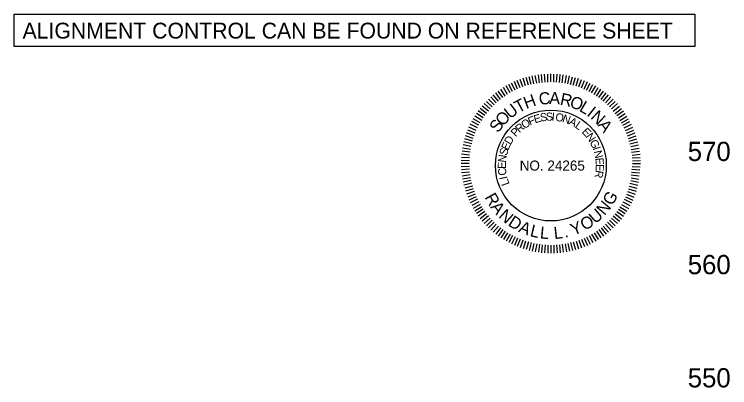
# Model space of a CAD drawing. Extents: x 1964377 to 1966966, y 1116414 to 1123213.
# Drawn here: x 1966634 to 1966949.9, y 1121376.7 to 1121541.6 of the extents above; entities that cross this region are included whole.
import ezdxf

# ---------------------------------------------------------------- set-up
doc = ezdxf.new("R2010")
doc.units = 0
for name, color, linetype in [('RD_DDB_Profile_Elev', 7, 'Continuous'), ('RD_Sketch1', 7, 'Continuous'), ('RD_TX_PEShield', 7, 'Continuous')]:
    doc.layers.add(name, color=color, linetype=linetype)

msp = doc.modelspace()

# ---------------------------------------------------------------- linework, layer by layer
at = {"layer": 'RD_Sketch1'}
msp.add_lwpolyline([(1966634.01, 1121541.61), (1966934.43, 1121541.61), (1966934.43, 1121527.35), (1966634.01, 1121527.35)], close=True, dxfattribs=at)
at = {"layer": 'RD_TX_PEShield'}
for p, q in [((1966869.64, 1121511.65), (1966869.52, 1121515.21)), ((1966869.64, 1121511.65), (1966869.52, 1121515.21)), ((1966870.9, 1121511.72), (1966870.9, 1121515.28)), ((1966870.9, 1121511.72), (1966870.9, 1121515.28)), ((1966872.15, 1121511.65), (1966872.28, 1121515.21)), ((1966872.15, 1121511.65), (1966872.28, 1121515.21)), ((1966857.41, 1121509.06), (1966856.08, 1121512.35)), ((1966857.41, 1121509.06), (1966856.08, 1121512.35)), ((1966858.59, 1121509.51), (1966857.37, 1121512.85)), ((1966858.59, 1121509.51), (1966857.37, 1121512.85)), ((1966859.76, 1121509.96), (1966858.66, 1121513.34)), ((1966859.76, 1121509.96), (1966858.66, 1121513.34)), ((1966860.98, 1121510.28), (1966860, 1121513.7)), ((1966860.98, 1121510.28), (1966860, 1121513.7)), ((1966862.19, 1121510.61), (1966861.33, 1121514.06)), ((1966862.19, 1121510.61), (1966861.33, 1121514.06)), ((1966863.4, 1121510.93), (1966862.66, 1121514.41)), ((1966863.4, 1121510.93), (1966862.66, 1121514.41)), ((1966864.65, 1121511.13), (1966864.03, 1121514.63)), ((1966864.65, 1121511.13), (1966864.03, 1121514.63)), ((1966865.89, 1121511.33), (1966865.39, 1121514.85)), ((1966865.89, 1121511.33), (1966865.39, 1121514.85)), ((1966867.13, 1121511.52), (1966866.76, 1121515.06)), ((1966867.13, 1121511.52), (1966866.76, 1121515.06)), ((1966868.39, 1121511.59), (1966868.14, 1121515.14)), ((1966868.39, 1121511.59), (1966868.14, 1121515.14)), ((1966873.41, 1121511.59), (1966873.66, 1121515.14)), ((1966873.41, 1121511.59), (1966873.66, 1121515.14)), ((1966874.67, 1121511.52), (1966875.04, 1121515.06)), ((1966874.67, 1121511.52), (1966875.04, 1121515.06)), ((1966875.91, 1121511.33), (1966876.4, 1121514.85)), ((1966875.91, 1121511.33), (1966876.4, 1121514.85)), ((1966877.15, 1121511.13), (1966877.77, 1121514.63)), ((1966877.15, 1121511.13), (1966877.77, 1121514.63)), ((1966878.39, 1121510.93), (1966879.13, 1121514.41)), ((1966878.39, 1121510.93), (1966879.13, 1121514.41)), ((1966878.39, 1121510.93), (1966879.13, 1121514.41)), ((1966879.61, 1121510.61), (1966880.47, 1121514.06)), ((1966879.61, 1121510.61), (1966880.47, 1121514.06)), ((1966879.61, 1121510.61), (1966880.47, 1121514.06)), ((1966880.82, 1121510.28), (1966881.8, 1121513.7)), ((1966880.82, 1121510.28), (1966881.8, 1121513.7)), ((1966880.82, 1121510.28), (1966881.8, 1121513.7)), ((1966882.04, 1121509.96), (1966883.14, 1121513.34)), ((1966882.04, 1121509.96), (1966883.14, 1121513.34)), ((1966882.04, 1121509.96), (1966883.14, 1121513.34)), ((1966883.21, 1121509.51), (1966884.43, 1121512.85)), ((1966883.21, 1121509.51), (1966884.43, 1121512.85)), ((1966883.21, 1121509.51), (1966884.43, 1121512.85)), ((1966884.38, 1121509.06), (1966885.72, 1121512.35)), ((1966884.38, 1121509.06), (1966885.72, 1121512.35)), ((1966884.38, 1121509.06), (1966885.72, 1121512.35)), ((1966851.82, 1121506.21), (1966849.94, 1121509.22)), ((1966851.82, 1121506.21), (1966849.94, 1121509.22)), ((1966852.88, 1121506.89), (1966851.1, 1121509.97)), ((1966852.88, 1121506.89), (1966851.1, 1121509.97)), ((1966854, 1121507.46), (1966852.33, 1121510.6)), ((1966854, 1121507.46), (1966852.33, 1121510.6)), ((1966855.12, 1121508.03), (1966853.56, 1121511.23)), ((1966855.12, 1121508.03), (1966853.56, 1121511.23)), ((1966856.24, 1121508.6), (1966854.79, 1121511.86)), ((1966856.24, 1121508.6), (1966854.79, 1121511.86)), ((1966885.56, 1121508.6), (1966887.01, 1121511.86)), ((1966885.56, 1121508.6), (1966887.01, 1121511.86)), ((1966885.56, 1121508.6), (1966887.01, 1121511.86)), ((1966886.68, 1121508.03), (1966888.24, 1121511.23)), ((1966886.68, 1121508.03), (1966888.24, 1121511.23)), ((1966886.68, 1121508.03), (1966888.24, 1121511.23)), ((1966887.8, 1121507.46), (1966889.47, 1121510.6)), ((1966887.8, 1121507.46), (1966889.47, 1121510.6)), ((1966887.8, 1121507.46), (1966889.47, 1121510.6)), ((1966888.92, 1121506.89), (1966890.7, 1121509.97)), ((1966888.92, 1121506.89), (1966890.7, 1121509.97)), ((1966888.92, 1121506.89), (1966890.7, 1121509.97)), ((1966889.98, 1121506.21), (1966891.86, 1121509.22)), ((1966889.98, 1121506.21), (1966891.86, 1121509.22)), ((1966889.98, 1121506.21), (1966891.86, 1121509.22)), ((1966847.76, 1121503.25), (1966845.47, 1121505.98)), ((1966847.76, 1121503.25), (1966845.47, 1121505.98)), ((1966848.73, 1121504.04), (1966846.54, 1121506.85)), ((1966848.73, 1121504.04), (1966846.54, 1121506.85)), ((1966849.71, 1121504.84), (1966847.62, 1121507.72)), ((1966849.71, 1121504.84), (1966847.62, 1121507.72)), ((1966850.77, 1121505.52), (1966848.78, 1121508.47)), ((1966850.77, 1121505.52), (1966848.78, 1121508.47)), ((1966891.03, 1121505.52), (1966893.02, 1121508.47)), ((1966891.03, 1121505.52), (1966893.02, 1121508.47)), ((1966891.03, 1121505.52), (1966893.02, 1121508.47)), ((1966892.09, 1121504.84), (1966894.18, 1121507.72)), ((1966892.09, 1121504.84), (1966894.18, 1121507.72)), ((1966892.09, 1121504.84), (1966894.18, 1121507.72)), ((1966893.06, 1121504.04), (1966895.25, 1121506.85)), ((1966893.06, 1121504.04), (1966895.25, 1121506.85)), ((1966893.06, 1121504.04), (1966895.25, 1121506.85)), ((1966894.04, 1121503.25), (1966896.33, 1121505.98)), ((1966894.04, 1121503.25), (1966896.33, 1121505.98)), ((1966894.04, 1121503.25), (1966896.33, 1121505.98)), ((1966845, 1121500.68), (1966842.44, 1121503.15)), ((1966845, 1121500.68), (1966842.44, 1121503.15)), ((1966845.89, 1121501.57), (1966843.42, 1121504.13)), ((1966845.89, 1121501.57), (1966843.42, 1121504.13)), ((1966846.78, 1121502.46), (1966844.4, 1121505.11)), ((1966846.78, 1121502.46), (1966844.4, 1121505.11)), ((1966895.02, 1121502.46), (1966897.4, 1121505.11)), ((1966895.02, 1121502.46), (1966897.4, 1121505.11)), ((1966895.02, 1121502.46), (1966897.4, 1121505.11)), ((1966895.91, 1121501.57), (1966898.38, 1121504.13)), ((1966895.91, 1121501.57), (1966898.38, 1121504.13)), ((1966895.91, 1121501.57), (1966898.38, 1121504.13)), ((1966896.8, 1121500.68), (1966899.35, 1121503.15)), ((1966896.8, 1121500.68), (1966899.35, 1121503.15)), ((1966896.8, 1121500.68), (1966899.35, 1121503.15)), ((1966842.53, 1121497.84), (1966839.73, 1121500.03)), ((1966842.53, 1121497.84), (1966839.73, 1121500.03)), ((1966843.32, 1121498.82), (1966840.6, 1121501.1)), ((1966843.32, 1121498.82), (1966840.6, 1121501.1)), ((1966844.11, 1121499.79), (1966841.47, 1121502.18)), ((1966844.11, 1121499.79), (1966841.47, 1121502.18)), ((1966897.69, 1121499.79), (1966900.33, 1121502.18)), ((1966897.69, 1121499.79), (1966900.33, 1121502.18)), ((1966897.69, 1121499.79), (1966900.33, 1121502.18)), ((1966898.48, 1121498.82), (1966901.2, 1121501.1)), ((1966898.48, 1121498.82), (1966901.2, 1121501.1)), ((1966898.48, 1121498.82), (1966901.2, 1121501.1)), ((1966899.27, 1121497.84), (1966902.07, 1121500.03)), ((1966899.27, 1121497.84), (1966902.07, 1121500.03)), ((1966899.27, 1121497.84), (1966902.07, 1121500.03)), ((1966840.37, 1121494.75), (1966837.35, 1121496.64)), ((1966840.37, 1121494.75), (1966837.35, 1121496.64)), ((1966841.05, 1121495.81), (1966838.1, 1121497.8)), ((1966841.05, 1121495.81), (1966838.1, 1121497.8)), ((1966841.74, 1121496.86), (1966838.86, 1121498.95)), ((1966841.74, 1121496.86), (1966838.86, 1121498.95)), ((1966900.06, 1121496.86), (1966902.94, 1121498.95)), ((1966900.06, 1121496.86), (1966902.94, 1121498.95)), ((1966900.06, 1121496.86), (1966902.94, 1121498.95)), ((1966900.74, 1121495.81), (1966903.69, 1121497.8)), ((1966900.74, 1121495.81), (1966903.69, 1121497.8)), ((1966900.74, 1121495.81), (1966903.69, 1121497.8)), ((1966901.43, 1121494.75), (1966904.44, 1121496.64)), ((1966901.43, 1121494.75), (1966904.44, 1121496.64)), ((1966901.43, 1121494.75), (1966904.44, 1121496.64)), ((1966839.11, 1121492.58), (1966835.97, 1121494.25)), ((1966839.11, 1121492.58), (1966835.97, 1121494.25)), ((1966839.68, 1121493.7), (1966836.6, 1121495.48)), ((1966839.68, 1121493.7), (1966836.6, 1121495.48)), ((1966902.11, 1121493.7), (1966905.2, 1121495.48)), ((1966902.11, 1121493.7), (1966905.2, 1121495.48)), ((1966902.11, 1121493.7), (1966905.2, 1121495.48)), ((1966902.69, 1121492.58), (1966905.83, 1121494.25)), ((1966902.69, 1121492.58), (1966905.83, 1121494.25)), ((1966902.69, 1121492.58), (1966905.83, 1121494.25)), ((1966837.52, 1121489.16), (1966834.22, 1121490.49)), ((1966837.52, 1121489.16), (1966834.22, 1121490.49)), ((1966837.97, 1121490.34), (1966834.72, 1121491.78)), ((1966837.97, 1121490.34), (1966834.72, 1121491.78)), ((1966838.54, 1121491.46), (1966835.35, 1121493.02)), ((1966838.54, 1121491.46), (1966835.35, 1121493.02)), ((1966903.26, 1121491.46), (1966906.45, 1121493.02)), ((1966903.26, 1121491.46), (1966906.45, 1121493.02)), ((1966903.26, 1121491.46), (1966906.45, 1121493.02)), ((1966903.83, 1121490.34), (1966907.08, 1121491.78)), ((1966903.83, 1121490.34), (1966907.08, 1121491.78)), ((1966903.83, 1121490.34), (1966907.08, 1121491.78)), ((1966904.28, 1121489.16), (1966907.57, 1121490.49)), ((1966904.28, 1121489.16), (1966907.57, 1121490.49)), ((1966904.28, 1121489.16), (1966907.57, 1121490.49)), ((1966836.62, 1121486.81), (1966833.23, 1121487.91)), ((1966836.62, 1121486.81), (1966833.23, 1121487.91)), ((1966837.07, 1121487.99), (1966833.73, 1121489.2)), ((1966837.07, 1121487.99), (1966833.73, 1121489.2)), ((1966904.73, 1121487.99), (1966908.07, 1121489.2)), ((1966904.73, 1121487.99), (1966908.07, 1121489.2)), ((1966904.73, 1121487.99), (1966908.07, 1121489.2)), ((1966905.18, 1121486.81), (1966908.57, 1121487.91)), ((1966905.18, 1121486.81), (1966908.57, 1121487.91)), ((1966905.18, 1121486.81), (1966908.57, 1121487.91)), ((1966835.64, 1121483.17), (1966832.16, 1121483.91)), ((1966835.64, 1121483.17), (1966832.16, 1121483.91)), ((1966835.97, 1121484.38), (1966832.52, 1121485.25)), ((1966835.97, 1121484.38), (1966832.52, 1121485.25)), ((1966836.29, 1121485.6), (1966832.87, 1121486.58)), ((1966836.29, 1121485.6), (1966832.87, 1121486.58)), ((1966905.5, 1121485.6), (1966908.92, 1121486.58)), ((1966905.5, 1121485.6), (1966908.92, 1121486.58)), ((1966905.5, 1121485.6), (1966908.92, 1121486.58)), ((1966905.83, 1121484.38), (1966909.28, 1121485.25)), ((1966905.83, 1121484.38), (1966909.28, 1121485.25)), ((1966905.83, 1121484.38), (1966909.28, 1121485.25)), ((1966906.16, 1121483.17), (1966909.64, 1121483.91)), ((1966906.16, 1121483.17), (1966909.64, 1121483.91)), ((1966906.16, 1121483.17), (1966909.64, 1121483.91)), ((1966835.25, 1121480.69), (1966831.73, 1121481.18)), ((1966835.25, 1121480.69), (1966831.73, 1121481.18)), ((1966835.44, 1121481.93), (1966831.94, 1121482.54)), ((1966835.44, 1121481.93), (1966831.94, 1121482.54)), ((1966906.35, 1121481.93), (1966909.85, 1121482.54)), ((1966906.35, 1121481.93), (1966909.85, 1121482.54)), ((1966906.35, 1121481.93), (1966909.85, 1121482.54)), ((1966906.55, 1121480.69), (1966910.07, 1121481.18)), ((1966906.55, 1121480.69), (1966910.07, 1121481.18)), ((1966906.55, 1121480.69), (1966910.07, 1121481.18)), ((1966834.99, 1121478.19), (1966831.44, 1121478.43)), ((1966834.99, 1121478.19), (1966831.44, 1121478.43)), ((1966835.05, 1121479.44), (1966831.51, 1121479.82)), ((1966835.05, 1121479.44), (1966831.51, 1121479.82)), ((1966906.75, 1121479.44), (1966910.29, 1121479.82)), ((1966906.75, 1121479.44), (1966910.29, 1121479.82)), ((1966906.75, 1121479.44), (1966910.29, 1121479.82)), ((1966906.81, 1121478.19), (1966910.36, 1121478.43)), ((1966906.81, 1121478.19), (1966910.36, 1121478.43)), ((1966906.81, 1121478.19), (1966910.36, 1121478.43)), ((1966834.85, 1121475.68), (1966831.29, 1121475.68)), ((1966834.85, 1121475.68), (1966831.29, 1121475.68)), ((1966834.92, 1121476.93), (1966831.37, 1121477.06)), ((1966834.92, 1121476.93), (1966831.37, 1121477.06)), ((1966834.92, 1121474.42), (1966831.37, 1121474.29)), ((1966834.92, 1121474.42), (1966831.37, 1121474.29)), ((1966906.81, 1121474.42), (1966910.36, 1121474.3)), ((1966906.81, 1121474.42), (1966910.36, 1121474.3)), ((1966906.88, 1121476.93), (1966910.43, 1121477.06)), ((1966906.88, 1121476.93), (1966910.43, 1121477.06)), ((1966906.88, 1121476.93), (1966910.43, 1121477.06)), ((1966906.94, 1121475.68), (1966910.5, 1121475.68)), ((1966906.94, 1121475.68), (1966910.5, 1121475.68)), ((1966906.94, 1121475.68), (1966910.5, 1121475.68)), ((1966834.99, 1121473.16), (1966831.44, 1121472.92)), ((1966834.99, 1121473.16), (1966831.44, 1121472.92)), ((1966835.05, 1121471.91), (1966831.51, 1121471.54)), ((1966835.05, 1121471.91), (1966831.51, 1121471.54)), ((1966906.55, 1121471.93), (1966910.07, 1121471.56)), ((1966906.55, 1121471.93), (1966910.07, 1121471.56)), ((1966906.68, 1121473.17), (1966910.21, 1121472.93)), ((1966906.68, 1121473.17), (1966910.21, 1121472.93)), ((1966835.25, 1121470.67), (1966831.73, 1121470.17)), ((1966835.25, 1121470.67), (1966831.73, 1121470.17)), ((1966835.44, 1121469.42), (1966831.94, 1121468.81)), ((1966835.44, 1121469.42), (1966831.94, 1121468.81)), ((1966835.64, 1121468.18), (1966832.16, 1121467.44)), ((1966835.64, 1121468.18), (1966832.16, 1121467.44)), ((1966906.16, 1121468.18), (1966909.64, 1121467.44)), ((1966906.16, 1121468.18), (1966909.64, 1121467.44)), ((1966906.29, 1121469.44), (1966909.78, 1121468.82)), ((1966906.29, 1121469.44), (1966909.78, 1121468.82)), ((1966906.42, 1121470.68), (1966909.93, 1121470.19)), ((1966906.42, 1121470.68), (1966909.93, 1121470.19)), ((1966835.97, 1121466.97), (1966832.52, 1121466.11)), ((1966835.97, 1121466.97), (1966832.52, 1121466.11)), ((1966836.29, 1121465.75), (1966832.87, 1121464.77)), ((1966836.29, 1121465.75), (1966832.87, 1121464.77)), ((1966905.5, 1121465.75), (1966908.92, 1121464.77)), ((1966905.5, 1121465.75), (1966908.92, 1121464.77)), ((1966905.83, 1121466.97), (1966909.28, 1121466.11)), ((1966905.83, 1121466.97), (1966909.28, 1121466.11)), ((1966836.62, 1121464.54), (1966833.23, 1121463.44)), ((1966837.07, 1121463.36), (1966833.73, 1121462.15)), ((1966837.07, 1121463.36), (1966833.73, 1121462.15)), ((1966837.52, 1121462.19), (1966834.22, 1121460.86)), ((1966837.52, 1121462.19), (1966834.22, 1121460.86)), ((1966904.28, 1121462.19), (1966907.57, 1121460.86)), ((1966904.28, 1121462.19), (1966907.57, 1121460.86)), ((1966904.73, 1121463.36), (1966908.07, 1121462.15)), ((1966904.73, 1121463.36), (1966908.07, 1121462.15)), ((1966905.18, 1121464.54), (1966908.57, 1121463.44)), ((1966905.18, 1121464.54), (1966908.57, 1121463.44)), ((1966837.97, 1121461.01), (1966834.72, 1121459.57)), ((1966837.97, 1121461.01), (1966834.72, 1121459.57)), ((1966838.54, 1121459.89), (1966835.35, 1121458.33)), ((1966838.54, 1121459.89), (1966835.35, 1121458.33)), ((1966839.11, 1121458.77), (1966835.97, 1121457.1)), ((1966839.11, 1121458.77), (1966835.97, 1121457.1)), ((1966902.69, 1121458.77), (1966905.83, 1121457.1)), ((1966902.69, 1121458.77), (1966905.83, 1121457.1)), ((1966903.26, 1121459.89), (1966906.45, 1121458.33)), ((1966903.26, 1121459.89), (1966906.45, 1121458.33)), ((1966903.83, 1121461.01), (1966907.08, 1121459.57)), ((1966903.83, 1121461.01), (1966907.08, 1121459.57)), ((1966839.68, 1121457.65), (1966836.6, 1121455.87)), ((1966839.68, 1121457.65), (1966836.6, 1121455.87)), ((1966840.37, 1121456.6), (1966837.35, 1121454.71)), ((1966840.37, 1121456.6), (1966837.35, 1121454.71)), ((1966841.05, 1121455.54), (1966838.1, 1121453.56)), ((1966841.05, 1121455.54), (1966838.1, 1121453.56)), ((1966900.74, 1121455.54), (1966903.69, 1121453.56)), ((1966900.74, 1121455.54), (1966903.69, 1121453.56)), ((1966901.43, 1121456.6), (1966904.44, 1121454.71)), ((1966901.43, 1121456.6), (1966904.44, 1121454.71)), ((1966902.11, 1121457.65), (1966905.2, 1121455.87)), ((1966902.11, 1121457.65), (1966905.2, 1121455.87)), ((1966841.74, 1121454.49), (1966838.86, 1121452.4)), ((1966841.74, 1121454.49), (1966838.86, 1121452.4)), ((1966842.53, 1121453.51), (1966839.73, 1121451.32)), ((1966842.53, 1121453.51), (1966839.73, 1121451.32)), ((1966843.32, 1121452.53), (1966840.6, 1121450.25)), ((1966843.32, 1121452.53), (1966840.6, 1121450.25)), ((1966898.48, 1121452.53), (1966901.2, 1121450.25)), ((1966898.48, 1121452.53), (1966901.2, 1121450.25)), ((1966899.27, 1121453.51), (1966902.07, 1121451.32)), ((1966899.27, 1121453.51), (1966902.07, 1121451.32)), ((1966900.06, 1121454.49), (1966902.94, 1121452.4)), ((1966900.06, 1121454.49), (1966902.94, 1121452.4)), ((1966844.11, 1121451.56), (1966841.47, 1121449.17)), ((1966844.11, 1121451.56), (1966841.47, 1121449.17)), ((1966845, 1121450.67), (1966842.44, 1121448.2)), ((1966845, 1121450.67), (1966842.44, 1121448.2)), ((1966845.89, 1121449.78), (1966843.42, 1121447.22)), ((1966845.89, 1121449.78), (1966843.42, 1121447.22)), ((1966846.78, 1121448.89), (1966844.4, 1121446.24)), ((1966846.78, 1121448.89), (1966844.4, 1121446.24)), ((1966895.02, 1121448.89), (1966897.4, 1121446.24)), ((1966895.91, 1121449.78), (1966898.38, 1121447.22)), ((1966895.91, 1121449.78), (1966898.38, 1121447.22)), ((1966896.8, 1121450.67), (1966899.35, 1121448.2)), ((1966896.8, 1121450.67), (1966899.35, 1121448.2)), ((1966897.69, 1121451.56), (1966900.33, 1121449.17)), ((1966897.69, 1121451.56), (1966900.33, 1121449.17)), ((1966847.76, 1121448.1), (1966845.47, 1121445.37)), ((1966847.76, 1121448.1), (1966845.47, 1121445.37)), ((1966848.73, 1121447.31), (1966846.54, 1121444.5)), ((1966848.73, 1121447.31), (1966846.54, 1121444.5)), ((1966849.71, 1121446.51), (1966847.62, 1121443.63)), ((1966849.71, 1121446.51), (1966847.62, 1121443.63)), ((1966850.77, 1121445.83), (1966848.78, 1121442.88)), ((1966850.77, 1121445.83), (1966848.78, 1121442.88)), ((1966891.03, 1121445.83), (1966893.02, 1121442.88)), ((1966891.03, 1121445.83), (1966893.02, 1121442.88)), ((1966892.09, 1121446.51), (1966894.18, 1121443.63)), ((1966892.09, 1121446.51), (1966894.18, 1121443.63)), ((1966893.06, 1121447.31), (1966895.25, 1121444.5)), ((1966893.06, 1121447.31), (1966895.25, 1121444.5)), ((1966894.04, 1121448.1), (1966896.33, 1121445.37)), ((1966894.04, 1121448.1), (1966896.33, 1121445.37)), ((1966851.82, 1121445.14), (1966849.94, 1121442.13)), ((1966851.82, 1121445.14), (1966849.94, 1121442.13)), ((1966852.88, 1121444.46), (1966851.1, 1121441.38)), ((1966852.88, 1121444.46), (1966851.1, 1121441.38)), ((1966854, 1121443.89), (1966852.33, 1121440.75)), ((1966854, 1121443.89), (1966852.33, 1121440.75)), ((1966855.12, 1121443.32), (1966853.56, 1121440.12)), ((1966855.12, 1121443.32), (1966853.56, 1121440.12)), ((1966856.24, 1121442.75), (1966854.79, 1121439.49)), ((1966856.24, 1121442.75), (1966854.79, 1121439.49)), ((1966885.56, 1121442.75), (1966887.01, 1121439.49)), ((1966885.56, 1121442.75), (1966887.01, 1121439.49)), ((1966886.68, 1121443.32), (1966888.24, 1121440.12)), ((1966886.68, 1121443.32), (1966888.24, 1121440.12)), ((1966887.8, 1121443.89), (1966889.47, 1121440.75)), ((1966887.8, 1121443.89), (1966889.47, 1121440.75)), ((1966888.92, 1121444.46), (1966890.7, 1121441.38)), ((1966888.92, 1121444.46), (1966890.7, 1121441.38)), ((1966889.98, 1121445.14), (1966891.86, 1121442.13)), ((1966889.98, 1121445.14), (1966891.86, 1121442.13)), ((1966857.41, 1121442.3), (1966856.08, 1121439)), ((1966857.41, 1121442.3), (1966856.08, 1121439)), ((1966858.59, 1121441.85), (1966857.37, 1121438.5)), ((1966858.59, 1121441.85), (1966857.37, 1121438.5)), ((1966859.76, 1121441.39), (1966858.66, 1121438.01)), ((1966859.76, 1121441.39), (1966858.66, 1121438.01)), ((1966860.98, 1121441.07), (1966860, 1121437.65)), ((1966860.98, 1121441.07), (1966860, 1121437.65)), ((1966862.19, 1121440.74), (1966861.33, 1121437.29)), ((1966862.19, 1121440.74), (1966861.33, 1121437.29)), ((1966863.4, 1121440.42), (1966862.66, 1121436.94)), ((1966863.4, 1121440.42), (1966862.66, 1121436.94)), ((1966864.65, 1121440.22), (1966864.03, 1121436.72)), ((1966864.65, 1121440.22), (1966864.03, 1121436.72)), ((1966865.89, 1121440.02), (1966865.39, 1121436.5)), ((1966865.89, 1121440.02), (1966865.39, 1121436.5)), ((1966867.13, 1121439.83), (1966866.76, 1121436.29)), ((1966867.13, 1121439.83), (1966866.76, 1121436.29)), ((1966868.39, 1121439.76), (1966868.14, 1121436.21)), ((1966868.39, 1121439.76), (1966868.14, 1121436.21)), ((1966869.64, 1121439.7), (1966869.52, 1121436.14)), ((1966869.64, 1121439.7), (1966869.52, 1121436.14)), ((1966870.9, 1121439.63), (1966870.9, 1121436.07)), ((1966870.9, 1121439.63), (1966870.9, 1121436.07)), ((1966872.15, 1121439.7), (1966872.28, 1121436.14)), ((1966872.15, 1121439.7), (1966872.28, 1121436.14)), ((1966873.41, 1121439.76), (1966873.66, 1121436.21)), ((1966873.41, 1121439.76), (1966873.66, 1121436.21)), ((1966874.67, 1121439.83), (1966875.04, 1121436.29)), ((1966874.67, 1121439.83), (1966875.04, 1121436.29)), ((1966875.91, 1121440.02), (1966876.4, 1121436.5)), ((1966875.91, 1121440.02), (1966876.4, 1121436.5)), ((1966877.15, 1121440.22), (1966877.77, 1121436.72)), ((1966877.15, 1121440.22), (1966877.77, 1121436.72)), ((1966878.39, 1121440.42), (1966879.13, 1121436.94)), ((1966878.39, 1121440.42), (1966879.13, 1121436.94)), ((1966879.61, 1121440.74), (1966880.47, 1121437.29)), ((1966879.61, 1121440.74), (1966880.47, 1121437.29)), ((1966880.82, 1121441.07), (1966881.8, 1121437.65)), ((1966880.82, 1121441.07), (1966881.8, 1121437.65)), ((1966882.04, 1121441.39), (1966883.14, 1121438.01)), ((1966882.04, 1121441.39), (1966883.14, 1121438.01)), ((1966883.21, 1121441.85), (1966884.43, 1121438.5)), ((1966883.21, 1121441.85), (1966884.43, 1121438.5)), ((1966884.38, 1121442.3), (1966885.72, 1121439)), ((1966884.38, 1121442.3), (1966885.72, 1121439))]:
    msp.add_line(p, q, dxfattribs=at)
msp.add_circle((1966870.9, 1121474.8), 24.48, dxfattribs=at)

# ---------------------------------------------------------------- texts
at = {"layer": 'RD_DDB_Profile_Elev'}
for s, p in [('570', (1966931.34, 1121476.8)), ('560', (1966931.34, 1121426.8)), ('550', (1966931.34, 1121376.8))]:
    msp.add_text(s, height=8.5, dxfattribs=at).set_placement(p)
at = {"layer": 'RD_Sketch1'}
msp.add_text('ALIGNMENT CONTROL CAN BE FOUND ON REFERENCE SHEET', height=7, dxfattribs=at).set_placement((1966637.66, 1121530.9))
at = {"layer": 'RD_TX_PEShield'}
for s, height, rotation, p in [('H', 5.34, 19.9102, (1966859.99, 1121499.72)), ('C', 5.34, 6.8832, (1966865.89, 1121501.54)), ('A', 5.34, 357.9448, (1966870.11, 1121501.99)), ('R', 5.34, 348.267, (1966874.69, 1121501.73)), ('T', 5.34, 28.0947, (1966856.56, 1121497.91)), ('O', 5.34, 339.3286, (1966878.83, 1121500.82)), ('L', 5.34, 329.6507, (1966883.09, 1121499.11)), ('U', 5.34, 37.7726, (1966852.88, 1121495.17)), ('I', 5.34, 321.4663, (1966886.43, 1121497.13)), ('O', 5.34, 47.4504, (1966849.71, 1121491.85)), ('F', 3.56, 23.0853, (1966861.71, 1121492.45)), ('E', 3.56, 16.1843, (1966863.9, 1121493.43)), ('S', 3.56, 8.6909, (1966866.39, 1121494.19)), ('S', 3.56, 1.79, (1966868.75, 1121494.59)), ('I', 3.56, 354.889, (1966871.14, 1121494.7)), ('O', 3.56, 350.4045, (1966872.7, 1121494.62)), ('N', 3.56, 341.7029, (1966875.68, 1121494.12)), ('N', 5.34, 317.0007, (1966888.12, 1121495.85)), ('S', 5.34, 54.9027, (1966847.67, 1121488.96)), ('R', 3.56, 39.8902, (1966857, 1121489.04)), ('O', 3.56, 31.7869, (1966859.14, 1121490.86)), ('A', 3.56, 333.0013, (1966878.54, 1121493.18)), ('L', 3.56, 324.2997, (1966881.24, 1121491.81)), ('A', 5.34, 307.3229, (1966891.41, 1121492.66)), ('P', 3.56, 46.7912, (1966855.38, 1121487.27)), ('E', 3.56, 313.2251, (1966884.31, 1121489.51)), ('D', 3.56, 59.074, (1966853.09, 1121483.68)), ('N', 3.56, 305.7317, (1966886.12, 1121487.63)), ('E', 3.56, 66.5674, (1966852.08, 1121481.29)), ('G', 3.56, 297.0301, (1966887.88, 1121485.18)), ('S', 3.56, 73.4683, (1966851.44, 1121478.98)), ('I', 3.56, 288.3285, (1966889.26, 1121482.49)), ('N', 3.56, 283.8441, (1966889.8, 1121481.03)), ('N', 3.56, 82.17, (1966851.03, 1121475.98)), ('E', 3.56, 275.1424, (1966890.53, 1121478.1)), ('E', 3.56, 89.6633, (1966851.04, 1121473.38)), ('E', 3.56, 267.6491, (1966890.79, 1121475.51)), ('C', 3.56, 97.7667, (1966851.44, 1121470.6)), ('R', 3.56, 260.1557, (1966890.72, 1121472.91)), ('I', 3.56, 102.2511, (1966851.83, 1121469.09)), ('L', 3.56, 109.7445, (1966852.74, 1121466.65)), ('R', 5.34, 299.1493, (1966841.5, 1121460.82)), ('G', 5.34, 60.1113, (1966898.01, 1121456.77)), ('N', 5.34, 50.4335, (1966894.59, 1121452.47)), ('A', 5.34, 308.0877, (1966844.02, 1121456.42)), ('N', 5.34, 317.7655, (1966847.5, 1121452.17)), ('U', 5.34, 40.7556, (1966890.5, 1121448.81)), ('D', 5.34, 327.4433, (1966851.63, 1121448.56)), ('O', 5.34, 31.0778, (1966885.85, 1121445.88)), ('A', 5.34, 337.1212, (1966856.32, 1121445.69)), ('Y', 5.34, 21.4, (1966880.78, 1121443.78)), ('L', 5.34, 346.799, (1966861.42, 1121443.65)), ('L', 5.34, 354.9835, (1966865.95, 1121442.62)), ('L', 5.34, 6.5171, (1966872.48, 1121442.28)), ('.', 5.34, 14.7016, (1966877.09, 1121442.84))]:
    msp.add_text(s, height=height, rotation=rotation, dxfattribs=at).set_placement(p)
msp.add_text('NO. 24265', height=4.45, dxfattribs=at).set_placement((1966857.14, 1121472.57))

doc.saveas('drawing.dxf')
